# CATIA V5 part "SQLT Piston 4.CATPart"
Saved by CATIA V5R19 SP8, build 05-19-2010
Part number: SQLT Piston 4
Publications: "Droite.1", "Droite.2", "Plan.1", "Plan.2"
Bounding box of the stored display mesh (mm): x -1000 to 1000, y -1250 to 1200, z -750 to 3600
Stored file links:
  C:\Users\ThinkMotion\Desktop\EU_thinkMotion\iao\IAO_MMS_Groupe3\fovide\fovide\SQLT Piston 4.CATPart
  C:\Users\ThinkMotion\Desktop\EU_thinkMotion\iao\IAO_MMS_Groupe3\fovide\fovide\fovide.CATProduct
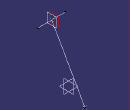
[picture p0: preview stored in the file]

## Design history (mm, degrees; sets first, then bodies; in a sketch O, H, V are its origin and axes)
External parameters (linked from other documents)
  `External.Rayon bielle` = 75 mm
  `External.Diamètre bielle` = 150 mm
Set1
  Point1 "Point.E": linked copy from another document
  Point2 "Point.B": linked copy from another document
Set2 "set piston 4"
  Line1: type PtPt, FirstPoint Point1, SecondPoint Point2
  Line2: type Normal, RefPoint Point1, RefSkin yz-plane, Start -1000, End 1000
  Plane1: type OffsetPt, RefPlane yz-plane, RefPoint Point1
  Plane2: type Offset, RefPlane Plane1, Offset 150 {= `External.Diamètre bielle`}, reversed
Body1 (main body)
